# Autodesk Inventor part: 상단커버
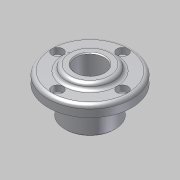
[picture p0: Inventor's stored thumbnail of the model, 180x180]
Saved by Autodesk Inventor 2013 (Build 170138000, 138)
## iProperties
Created: 2014-03
Part Number: 상단커버
Document SubType Name: Modeling
Designer: SeoGD™[esajin.kr]
Density: 1 g/cm^3
Material: 일반
Author: SeoGD™[esajin.kr]
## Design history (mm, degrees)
sketch "스케치1"
  geometry: C1 r 22.5 at (0, 0) reference; C2 r 13.5 at (0, 0) reference; 1 further point
  node "참조1"
  node "참조2"
extrude "돌출1" new body sketch "스케치1" distance "d0" = 6; taper "d1" = 0 deg
extrude "돌출2" join sketch "스케치1" distance "d2" = 15; taper "d3" = 0 deg
sketch "스케치2"
  geometry: C1 r 7.5 at (0, 0); 1 further point
  constraints: 1 centre point, 1 coincident
  dimensions: "d4" = 15 diameter of C1
extrude "돌출3" cut sketch "스케치2" stored distance "d5" = 15; taper "d6" = 0 deg
sketch "스케치3"
  geometry: C1 r 7.5 at (0, 0) reference; C2 r 1.23 at (0, 17.5) reference; C3 r 12.5 at (0, 0); 1 further point
  constraints: 1 centre point, 1 coincident
  dimensions: "d7" = 25 diameter of C3
  node "참조3"
extrude "돌출4" join sketch "스케치3" distance "d8" = 3; taper "d9" = 0 deg
hole "구멍1" sketch "스케치3" diameter "d10" = 3.4; stored, may be unused: countersink angle "d14" = 90 deg, drill point angle "d16" = 118 deg; dims "d11" = 6, "d12" = 6, "d13" = 3.3, "d15" = 8
fillet "모깎기1" dims "d20" = 2
chamfer "모따기1" distance "d21" = 0.5; stored, may be unused: second distance "d22" = 2, angle "d23" = 45 deg
node "솔리드1"
pattern_circular "원형 패턴1" dims angle "d18" = 360 deg
